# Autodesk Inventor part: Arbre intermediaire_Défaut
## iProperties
Shininess: 64.0
Length Units: 11269
Angle Units: 11279
Time Units: 11290
Mass Units: 11283
Length Display Precision: 3
Angle Display Precision: 2
Compacted: True
Part Number: Arbre intermediaire_Défaut
Document SubType Name: Modeling
Created: 2006-01
Material: Par défaut
Designer: Fricot
Density: 0.0
Volumn: 0.0
Area: 0.0
PropertySet Name: Model Information
Control State: 0
Master: False
Checked Out: False
Author: Fricot
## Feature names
1. Base1
